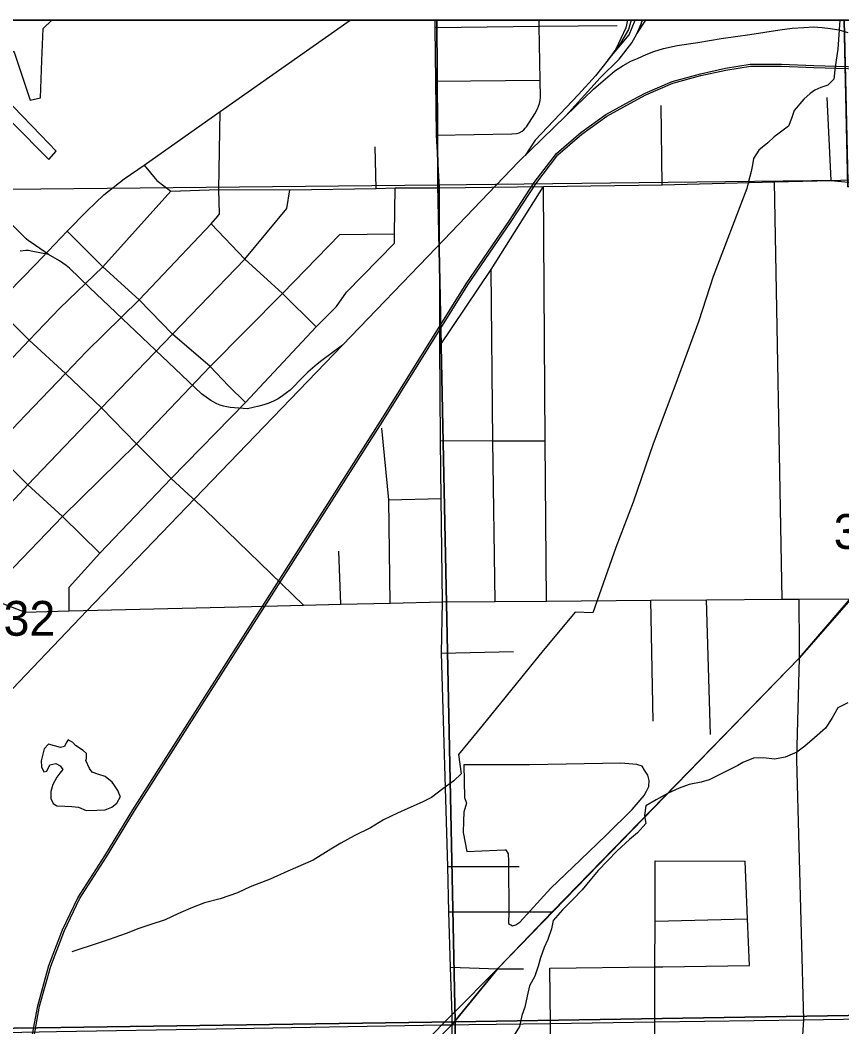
# Model space of a CAD drawing. Extents: x 0 to 40.2, y 0 to 22.
# Drawn here: x 4.597 to 5.585, y 19.689 to 20.9 of the extents above; entities that cross this region are included whole.
import ezdxf

# ---------------------------------------------------------------- set-up
doc = ezdxf.new("R2010")
doc.units = 0
for name, color, linetype in [('GM_X_Adjacent_County', 7, 'Continuous'), ('GM_X_City_Street', 7, 'Continuous'), ('GM_X_Corporation', 7, 'Continuous'), ('GM_X_Interchange_Ramps', 7, 'Continuous'), ('GM_X_Major_Lake_Text', 7, 'Continuous'), ('GM_X_Major_River', 7, 'Continuous'), ('GM_X_Minor_Lake', 7, 'Continuous'), ('GM_X_Minor_Lake_Text', 7, 'Continuous'), ('GM_X_Township_Road', 7, 'Continuous'), ('GM_X_Unincorporated_Location', 7, 'Continuous')]:
    doc.layers.add(name, color=color, linetype=linetype)

msp = doc.modelspace()

# ---------------------------------------------------------------- linework, layer by layer
at = {"layer": 'GM_X_Adjacent_County'}
msp.add_line((2.1, 20.9), (8.9, 20.9), dxfattribs=at)
at = {"layer": 'GM_X_Corporation'}
for points in [[(8.9, 17.4415), (8.9, 20.9), (2.1, 20.9)], [(4.4314, 18.6782), (4.6192, 18.6797), (4.6199, 19.1791), (4.6987, 19.2675), (4.8372, 19.4112), (5.1165, 19.6915), (5.1717, 19.759), (5.5342, 20.1328), (5.6046, 20.2128), (5.8375, 20.216), (5.8399, 20.2611), (5.844, 20.2921), (5.8506, 20.3189), (5.8744, 20.387), (5.8909, 20.4334), (5.9081, 20.4755), (5.9235, 20.5032), (5.9538, 20.5583), (5.9919, 20.6239), (6.0382, 20.7021), (5.5927, 20.6995), (5.588, 20.9), (2.1, 20.9)], [(4.8372, 19.4112), (5.1045, 19.6913), (5.1161, 19.7032), (5.1717, 19.759), (5.2371, 19.8275), (5.5342, 20.1328), (5.5958, 20.2042), (5.6082, 20.2186), (5.8383, 20.2215), (5.8417, 20.3082), (5.8496, 20.324), (5.8654, 20.3636), (5.8733, 20.4032), (5.8971, 20.4507), (5.9129, 20.4903), (5.9524, 20.5694), (5.9761, 20.609), (6.0157, 20.6644), (6.0382, 20.7021), (5.8731, 20.7019), (5.5927, 20.6995), (5.5925, 20.7054), (5.588, 20.9), (2.1, 20.9)], [(8.9, 17.4415), (8.9, 20.9), (5.588, 20.9), (5.5927, 20.6995), (6.0382, 20.7021), (5.9919, 20.6239), (5.9538, 20.5583), (5.9235, 20.5032), (5.9081, 20.4755), (5.8909, 20.4334), (5.8744, 20.387), (5.8506, 20.3189), (5.844, 20.2921), (5.8399, 20.2611), (5.8375, 20.216), (5.6046, 20.2128), (5.5342, 20.1328), (5.1717, 19.759), (5.1165, 19.6915), (4.8372, 19.4112)], [(8.9, 20.9), (5.588, 20.9), (5.5925, 20.7054), (5.5927, 20.6995), (5.8731, 20.7019), (6.0382, 20.7021), (6.0157, 20.6644), (5.9761, 20.609), (5.9524, 20.5694), (5.9129, 20.4903), (5.8971, 20.4507), (5.8733, 20.4032), (5.8654, 20.3636), (5.8496, 20.324), (5.8417, 20.3082), (5.8383, 20.2215), (5.6082, 20.2186), (5.5958, 20.2042), (5.5342, 20.1328), (5.2371, 19.8275), (5.1717, 19.759), (5.1161, 19.7032), (5.1045, 19.6913), (4.8372, 19.4112)]]:
    msp.add_lwpolyline(points, dxfattribs=at)
for points in [[(5.0982, 20.9), (4.102, 20.9), (4.1041, 20.6918), (5.0991, 20.7019)], [(6.1006, 20.9), (5.0982, 20.9), (5.0991, 20.7019), (6.1033, 20.7135)], [(6.1033, 20.7135), (6.116, 19.7108), (5.1201, 19.6946), (5.0991, 20.7019)], [(5.0991, 20.7019), (5.1201, 19.6946), (4.1148, 19.68), (4.1046, 20.6218), (4.1041, 20.6918)], [(5.1201, 19.6946), (6.116, 19.7108), (6.1341, 18.7062), (5.1306, 18.6912)], [(4.1148, 19.68), (5.1201, 19.6946), (5.1306, 18.6912), (4.119, 18.6842)]]:
    msp.add_lwpolyline(points, close=True, dxfattribs=at)
at = {"layer": 'GM_X_Interchange_Ramps'}
msp.add_lwpolyline([(4.4541, 20.7316), (4.4748, 20.7533), (4.4936, 20.7724), (4.5261, 20.7393), (4.5654, 20.7031), (4.5739, 20.7117), (4.5477, 20.739), (4.5055, 20.7817), (4.5443, 20.8199), (4.5872, 20.7768), (4.6313, 20.7321), (4.6402, 20.7422), (4.6215, 20.7615), (4.5883, 20.7961), (4.5565, 20.8311), (4.5891, 20.8626), (4.6088, 20.8038), (4.6213, 20.8067), (4.6227, 20.8515), (4.6244, 20.8898), (4.6348, 20.9)], dxfattribs=at)
at = {"layer": 'GM_X_Major_Lake_Text'}
msp.add_line((5.1167, 19.691), (5.1364, 19.6912), dxfattribs=at)
for points in [[(4.208, 20.2451), (4.2642, 20.2768), (4.3144, 20.3047), (4.4009, 20.3905), (4.4768, 20.4677), (4.5211, 20.5145), (4.5659, 20.5559), (4.6151, 20.6058), (4.6532, 20.6459), (4.6773, 20.6704), (4.6974, 20.6899), (4.7219, 20.7091), (4.7458, 20.7255), (4.8158, 20.7748), (4.8374, 20.79), (4.994, 20.9)], [(4.7458, 20.7255), (4.7613, 20.7069), (4.7781, 20.6941), (4.836, 20.6961), (4.9214, 20.6959), (5.025, 20.6974), (5.0481, 20.6981), (5.1011, 20.6981), (5.2263, 20.6999), (5.3692, 20.7019), (5.5042, 20.7054), (5.5724, 20.7071), (5.5928, 20.7049), (5.6113, 20.7051)], [(4.3144, 20.3047), (4.3435, 20.2917), (4.3894, 20.2729), (4.4341, 20.2534), (4.5084, 20.2251), (4.5711, 20.1996), (4.6027, 20.1877), (4.6556, 20.189), (4.8594, 20.194), (4.9376, 20.1959), (4.9825, 20.197), (5.0418, 20.1984), (5.1048, 20.1999), (5.1681, 20.2004), (5.2299, 20.2009), (5.3555, 20.2019), (5.4225, 20.2024), (5.5134, 20.2031), (5.534, 20.2032), (5.596, 20.2037), (5.6074, 20.2038)], [(5.1364, 19.6912), (5.2347, 19.6927), (5.3603, 19.6946), (5.5394, 19.6972), (5.6108, 19.6983), (5.6774, 19.6993), (5.7379, 19.7002), (5.8031, 19.7031), (5.8652, 19.7021), (5.9286, 19.703), (5.9875, 19.7039), (6.1177, 19.7069), (7.0829, 19.7189)], [(3.6156, 19.4174), (3.6753, 19.4382), (3.7403, 19.4567), (3.8018, 19.4749), (3.8624, 19.4921), (3.9252, 19.5089), (3.9827, 19.5231), (4.0225, 19.5337), (4.149, 19.5748), (4.191, 19.5885), (4.3232, 19.6297), (4.3386, 19.6349), (4.3427, 19.6363), (4.3493, 19.6382), (4.4443, 19.6659), (4.4771, 19.6761), (4.505, 19.6806), (4.5246, 19.6809), (4.5781, 19.6818), (4.6407, 19.6829), (4.8325, 19.6861), (5.1048, 19.6908), (5.1167, 19.691)], [(5.1191, 19.1918), (5.1184, 19.2372), (5.1226, 19.2497), (5.1217, 19.3167), (5.1209, 19.3775), (5.1167, 19.691)]]:
    msp.add_lwpolyline(points, dxfattribs=at)
at = {"layer": 'GM_X_Major_River'}
for p, q in [((5.3388, 20.8836), (5.3493, 20.9)), ((5.3449, 20.9), (5.3428, 20.8925)), ((5.3136, 20.8649), (5.304, 20.8521))]:
    msp.add_line(p, q, dxfattribs=at)
for points in [[(5.2532, 20.7849), (5.2946, 20.8305), (5.3175, 20.8531), (5.3326, 20.8727), (5.3388, 20.8836), (5.344, 20.8954), (5.3453, 20.9)], [(5.304, 20.8521), (5.3293, 20.8824), (5.3365, 20.9)], [(5.3275, 20.9), (5.3253, 20.8909), (5.3136, 20.8649)], [(5.3318, 20.9), (5.3286, 20.8889), (5.3191, 20.8722), (5.3136, 20.8649)], [(5.2532, 20.7849), (5.2867, 20.817), (5.3122, 20.8389), (5.3222, 20.8454), (5.3315, 20.8506), (5.3401, 20.8544), (5.3498, 20.8588), (5.359, 20.8624), (5.3706, 20.8658), (5.3871, 20.8693), (5.4121, 20.8731), (5.4401, 20.8777), (5.4747, 20.8829), (5.5109, 20.8882), (5.5254, 20.8903), (5.5396, 20.8912), (5.5512, 20.8918), (5.5617, 20.8912), (5.5716, 20.8899), (5.5817, 20.8882), (5.5924, 20.8853)], [(5.304, 20.8521), (5.2888, 20.833), (5.2685, 20.8107), (5.2162, 20.7556), (5.2043, 20.7371)], [(4.6105, 19.6732), (4.6179, 19.714), (4.6312, 19.7623), (4.6479, 19.8055), (4.6662, 19.8438), (4.6985, 19.8944), (4.7325, 19.9499), (5.033, 20.422), (5.1332, 20.5827), (5.1854, 20.6589), (5.2152, 20.7045), (5.2419, 20.7396), (5.2712, 20.7646), (5.3012, 20.7863), (5.3344, 20.8046), (5.3486, 20.8121), (5.3811, 20.8263), (5.4153, 20.8354), (5.4452, 20.8421), (5.4752, 20.8471), (5.5127, 20.8471), (5.5517, 20.8455), (5.6063, 20.8438)], [(4.6128, 19.6729), (4.6202, 19.7135), (4.6335, 19.7615), (4.65, 19.8046), (4.6682, 19.8427), (4.7005, 19.8932), (4.7345, 19.9487), (5.035, 20.4208), (5.1352, 20.5814), (5.1873, 20.6576), (5.2171, 20.7032), (5.2436, 20.738), (5.2726, 20.7628), (5.3024, 20.7843), (5.3355, 20.8026), (5.3496, 20.81), (5.3819, 20.8241), (5.4158, 20.8332), (5.4456, 20.8398), (5.4754, 20.8448), (5.5127, 20.8448), (5.5516, 20.8431), (5.6062, 20.8415)], [(4.5706, 20.0782), (4.677, 20.1891), (4.8068, 20.3243), (4.9846, 20.5087), (5.0973, 20.6259), (5.1423, 20.6728), (5.1965, 20.7295), (5.2532, 20.7849)], [(4.6309, 20.6178), (4.61, 20.6323), (4.6069, 20.6346), (4.604, 20.637), (4.6012, 20.6397), (4.5415, 20.6987)], [(4.6309, 20.6178), (4.61, 20.6221), (4.6068, 20.6226), (4.6037, 20.6227), (4.6005, 20.6225), (4.5967, 20.622)], [(4.9846, 20.5087), (4.9599, 20.4906), (4.954, 20.486), (4.9483, 20.4813), (4.9428, 20.4763), (4.9375, 20.471), (4.9216, 20.4548), (4.9173, 20.4514), (4.9123, 20.4477), (4.9071, 20.4444), (4.9016, 20.4416), (4.8959, 20.4391), (4.89, 20.4371), (4.8841, 20.4355), (4.8703, 20.4324), (4.8496, 20.434), (4.8454, 20.4345), (4.8413, 20.4354), (4.8373, 20.4366), (4.8334, 20.4382), (4.8297, 20.4402), (4.8262, 20.4424), (4.815, 20.4502), (4.6802, 20.5784), (4.6561, 20.6014), (4.6523, 20.6047), (4.6483, 20.6077), (4.644, 20.6104), (4.6309, 20.6178)]]:
    msp.add_lwpolyline(points, dxfattribs=at)
at = {"layer": 'GM_X_Minor_Lake'}
for points in [[(5.5828, 20.9), (5.5803, 20.8652), (5.5773, 20.844), (5.5756, 20.8288), (5.5683, 20.8217), (5.56, 20.8188), (5.5527, 20.8159), (5.547, 20.8118), (5.5397, 20.8047), (5.5278, 20.7911), (5.5246, 20.7817), (5.5211, 20.7723), (5.5081, 20.7626), (5.5039, 20.7596), (5.4962, 20.7525), (5.4855, 20.7435), (5.4789, 20.7334), (5.4777, 20.7258), (5.4761, 20.7178), (5.4732, 20.7057), (5.4709, 20.6974), (5.4304, 20.5917)], [(5.4304, 20.5917), (5.4131, 20.538), (5.3844, 20.4594), (5.3584, 20.3903), (5.3344, 20.32), (5.3136, 20.2653), (5.2856, 20.1867), (5.2644, 20.1874), (5.226, 20.1416), (5.1936, 20.1014), (5.152, 20.0504), (5.1243, 20.0162), (5.1274, 19.993), (5.1186, 19.9848), (5.1052, 19.9751), (5.0918, 19.9647), (5.0803, 19.9588), (5.0632, 19.9514), (5.0506, 19.9455), (5.0339, 19.9378), (5.0182, 19.9281), (4.9988, 19.9185), (4.9827, 19.9096), (4.9705, 19.9022), (4.9491, 19.8892), (4.919, 19.876), (4.8977, 19.8661), (4.8733, 19.8569), (4.8581, 19.8499), (4.8375, 19.8426), (4.8185, 19.8376), (4.8022, 19.8313), (4.7865, 19.8244), (4.7713, 19.8174), (4.7527, 19.8115), (4.7397, 19.8068), (4.7245, 19.8009), (4.7039, 19.7936), (4.6918, 19.7896), (4.6591, 19.7787)], [(5.5925, 20.0783), (5.5803, 20.0724), (5.5733, 20.0596), (5.5655, 20.0479), (5.5525, 20.0363), (5.5406, 20.0262), (5.5311, 20.0192), (5.5173, 20.0129), (5.5041, 20.0108), (5.4912, 20.0121), (5.4791, 20.0119), (5.4661, 20.0068), (5.46, 20.0031), (5.4257, 19.9857), (5.4162, 19.9832), (5.4018, 19.98), (5.3896, 19.9756), (5.3763, 19.9697), (5.3621, 19.9616), (5.3496, 19.9545), (5.3479, 19.9428), (5.3493, 19.9333), (5.3396, 19.922), (5.3297, 19.9142), (5.3151, 19.9004)], [(5.3151, 19.9004), (5.3032, 19.8884), (5.2921, 19.8768), (5.284, 19.867), (5.2728, 19.8535), (5.2617, 19.8419), (5.2494, 19.8292), (5.2382, 19.8164), (5.2362, 19.8066), (5.2315, 19.7937), (5.2272, 19.7839), (5.2229, 19.7718), (5.2201, 19.7616), (5.2158, 19.7495), (5.2095, 19.7379), (5.2067, 19.7254), (5.2039, 19.7121), (5.2004, 19.7023), (5.1975, 19.689), (5.1902, 19.6774)]]:
    msp.add_lwpolyline(points, dxfattribs=at)
at = {"layer": 'GM_X_Minor_Lake_Text'}
for p, q in [((4.6671, 19.9529), (4.6761, 19.9489)), ((5.271, 19.8896), (5.3017, 19.9192))]:
    msp.add_line(p, q, dxfattribs=at)
for points in [[(4.6761, 19.9489), (4.689, 19.9495), (4.6992, 19.9497), (4.7072, 19.9531), (4.713, 19.9579), (4.7176, 19.9658), (4.7169, 19.967), (4.7143, 19.9731), (4.7095, 19.98), (4.7073, 19.983), (4.699, 19.99), (4.6915, 19.9924), (4.6836, 19.9952), (4.6802, 19.9994), (4.6758, 20.0089), (4.6766, 20.0116), (4.6767, 20.0173), (4.6725, 20.0211), (4.6635, 20.0273), (4.6602, 20.0308), (4.6545, 20.0339), (4.6522, 20.0305), (4.6503, 20.026), (4.6453, 20.0249), (4.631, 20.0286), (4.6256, 20.0233), (4.624, 20.0165), (4.622, 20.0086), (4.6223, 20.0013), (4.6252, 19.9956), (4.629, 19.9963), (4.6325, 20.0039), (4.6398, 20.0053), (4.645, 20.0025), (4.648, 19.9983), (4.6445, 19.9938), (4.6411, 19.9889), (4.636, 19.9803), (4.6336, 19.9719), (4.6335, 19.9632), (4.6365, 19.9575), (4.641, 19.9544), (4.6504, 19.9542), (4.6588, 19.9537), (4.6671, 19.9529)], [(5.3017, 19.9192), (5.3332, 19.9502), (5.3474, 19.9671), (5.3502, 19.972), (5.3533, 19.9777), (5.3534, 19.9849), (5.3519, 19.9913), (5.3479, 19.9975), (5.3449, 20.0021), (5.3385, 20.0044), (5.3196, 20.0058), (5.2097, 20.004), (5.1306, 20.004), (5.1315, 19.9645), (5.1337, 19.9576), (5.1306, 19.947), (5.13, 19.936), (5.1298, 19.9224), (5.1341, 19.8995), (5.1701, 19.9013), (5.1799, 19.9015), (5.1811, 19.9015), (5.1837, 19.8969), (5.1843, 19.8878), (5.1846, 19.8229), (5.1841, 19.8168), (5.1844, 19.813), (5.1889, 19.8103), (5.1931, 19.8114), (5.1981, 19.8147), (5.2354, 19.8556), (5.271, 19.8896)]]:
    msp.add_lwpolyline(points, dxfattribs=at)
at = {"layer": 'GM_X_Township_Road'}
msp.add_lwpolyline([(2.1, 20.9), (8.9, 20.9), (8.9, 14.1), (2.1, 14.1)], close=True, dxfattribs=at)
at = {"layer": 'GM_X_Unincorporated_Location'}
for p, q in [((5.0967, 20.8264), (5.2224, 20.8279)), ((5.5724, 20.7071), (5.5677, 20.8069)), ((5.3692, 20.7019), (5.3681, 20.7974)), ((5.0976, 20.7616), (5.1882, 20.7631)), ((5.025, 20.6974), (5.0238, 20.7474)), ((5.5134, 20.2031), (5.5042, 20.7054)), ((5.0405, 20.3227), (5.1034, 20.3245)), ((4.9825, 20.197), (4.9801, 20.261)), ((5.3582, 20.0563), (5.3555, 20.2019)), ((5.4273, 20.0403), (5.4225, 20.2024)), ((5.1035, 20.1382), (5.1903, 20.1402)), ((5.5311, 20.0109), (5.5344, 20.1323)), ((5.1111, 19.8817), (5.1971, 19.8814)), ((5.3609, 19.8884), (5.4688, 19.8879)), ((5.1127, 19.827), (5.2374, 19.8269)), ((5.3607, 19.8157), (5.4719, 19.8185)), ((5.1147, 19.7604), (5.172, 19.7585)), ((5.172, 19.7585), (5.2023, 19.7582))]:
    msp.add_line(p, q, dxfattribs=at)
for points in [[(5.1167, 19.691), (5.1164, 19.7027), (5.1147, 19.7604), (5.1127, 19.827), (5.1111, 19.8817), (5.1035, 20.1382), (5.1048, 20.1999), (5.1034, 20.3245), (5.1025, 20.394), (5.1015, 20.5082), (5.1011, 20.6981), (5.0976, 20.7616), (5.0967, 20.8264), (5.096, 20.8911), (5.0959, 20.9)], [(5.1882, 20.7631), (5.1938, 20.7634), (5.1972, 20.7643), (5.2006, 20.7663), (5.2026, 20.7681), (5.2044, 20.7699), (5.2059, 20.7716), (5.216, 20.7871), (5.219, 20.7934), (5.2214, 20.7997), (5.2222, 20.8032), (5.2226, 20.8074), (5.2224, 20.8279), (5.2213, 20.8927), (5.2213, 20.9)], [(5.096, 20.8911), (5.2213, 20.8927), (5.3149, 20.8937)], [(4.4341, 20.2534), (4.4824, 20.2989), (4.4889, 20.3057), (4.5635, 20.3834), (4.6033, 20.4248), (4.6512, 20.4747), (4.6767, 20.5014), (4.74, 20.5634), (4.8265, 20.6547), (4.8346, 20.6643), (4.8367, 20.667), (4.836, 20.6961), (4.8374, 20.79)], [(4.3319, 20.123), (4.3894, 20.2729), (4.3956, 20.289), (4.4467, 20.3453), (4.5211, 20.4236), (4.6076, 20.5147), (4.6444, 20.5534), (4.6962, 20.6031), (4.7781, 20.6941)], [(4.5334, 20.263), (4.606, 20.341), (4.6947, 20.4334), (4.7801, 20.5221), (4.867, 20.6123), (4.9175, 20.6735), (4.9214, 20.6959)], [(4.6556, 20.189), (4.6557, 20.2177), (4.6925, 20.2586), (4.7786, 20.3484), (4.8677, 20.44), (4.9527, 20.5311), (4.9774, 20.5553), (4.9895, 20.5726), (5.047, 20.6318), (5.0473, 20.6429), (5.0481, 20.6981)], [(5.1015, 20.5082), (5.1634, 20.5998), (5.2263, 20.6999)], [(5.2299, 20.2009), (5.2282, 20.3938), (5.2263, 20.6999)], [(4.8677, 20.44), (4.8475, 20.4599), (4.8254, 20.4831), (4.7801, 20.5221), (4.74, 20.5634), (4.6962, 20.6031), (4.6532, 20.6459)], [(4.9527, 20.5311), (4.9122, 20.5711), (4.867, 20.6123), (4.8265, 20.6547)], [(4.5711, 20.1996), (4.5794, 20.2314), (4.5799, 20.232), (4.6478, 20.3028), (4.7366, 20.3903), (4.8254, 20.4831), (4.9122, 20.5711), (4.9814, 20.6421), (5.0473, 20.6429)], [(5.1681, 20.2004), (5.1656, 20.3938), (5.1634, 20.5998)], [(4.9376, 20.1959), (4.8195, 20.3108), (4.7786, 20.3484), (4.7366, 20.3903), (4.6947, 20.4334), (4.6512, 20.4747), (4.6076, 20.5147), (4.5659, 20.5559)], [(4.6925, 20.2586), (4.6478, 20.3028), (4.606, 20.341), (4.5635, 20.3834), (4.5211, 20.4236), (4.4768, 20.4677)], [(5.0418, 20.1984), (5.0405, 20.3227), (5.0319, 20.409)], [(5.1025, 20.394), (5.1656, 20.3938), (5.2282, 20.3938)], [(5.5344, 20.1323), (5.5344, 20.1448), (5.534, 20.2032)], [(5.5394, 19.6972), (5.5311, 20.0098), (5.5311, 20.0109)], [(5.3689, 19.1945), (5.3644, 19.2538), (5.3638, 19.3245), (5.3632, 19.3818), (5.3626, 19.4483), (5.362, 19.5136), (5.3614, 19.5793), (5.3609, 19.6337), (5.3603, 19.6946), (5.3605, 19.7608), (5.3607, 19.8157), (5.3609, 19.8884)], [(5.4744, 19.7622), (5.4719, 19.8185), (5.4688, 19.8879)], [(5.2341, 19.7593), (5.3605, 19.7608), (5.3699, 19.7609), (5.4744, 19.7622)], [(5.2464, 18.8112), (5.2454, 18.8502), (5.2439, 18.9109), (5.2433, 18.9336), (5.2421, 18.9797), (5.2407, 19.0356), (5.2406, 19.0378), (5.2389, 19.1059), (5.2447, 19.1919), (5.2434, 19.2545), (5.237, 19.3204), (5.2371, 19.3796), (5.2373, 19.4459), (5.2374, 19.5107), (5.2374, 19.5119), (5.2363, 19.5738), (5.2352, 19.6326), (5.2352, 19.6341), (5.2347, 19.6927), (5.2341, 19.7593)], [(5.5378, 19.6727), (5.5394, 19.6972)]]:
    msp.add_lwpolyline(points, dxfattribs=at)

# ---------------------------------------------------------------- texts
at = {"layer": 'GM_X_City_Street'}
for s, p in [('33', (5.5755, 20.2638)), ('32', (4.5768, 20.1592))]:
    msp.add_text(s, height=0.04186, rotation=0, dxfattribs=at).set_placement(p)

doc.saveas('drawing.dxf')
